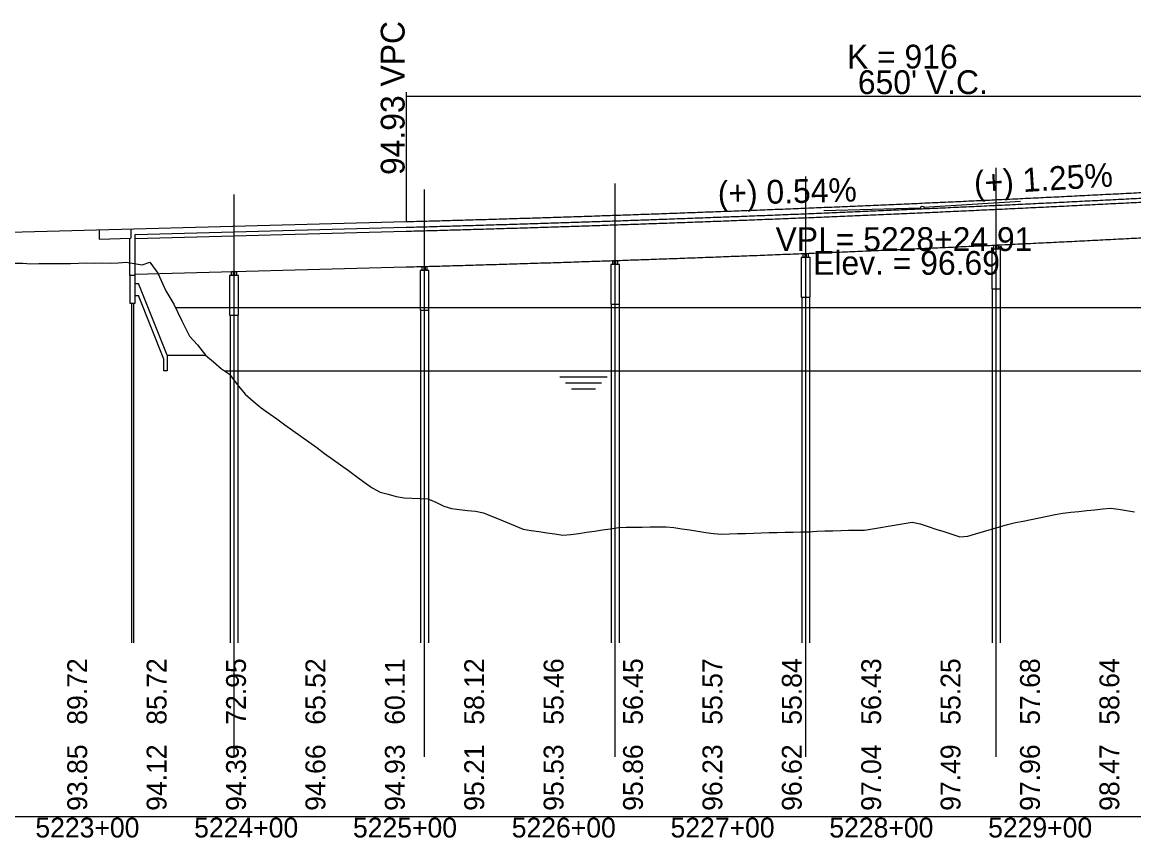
# Model space of a CAD drawing. Extents: x 2121671 to 2169879, y 557274 to 599957.
# Drawn here: x 2151826 to 2152526, y 579173 to 579687 of the extents above; entities that cross this region are included whole.
import ezdxf

# ---------------------------------------------------------------- set-up
doc = ezdxf.new("R2010")
doc.units = 0
for name, color, linetype in [('BR_CENTER LINES', 7, 'Continuous'), ('BR_CONCRETE', 7, 'Continuous'), ('BR_DETAILS', 7, 'Continuous'), ('BR_PRESTRESSED BEAM', 7, 'Continuous'), ('BR_STRUCTURAL STEEL', 7, 'Continuous'), ('RD_DDB_GradeTX', 7, 'Continuous'), ('RD_DDB_Profile_Elev', 7, 'Continuous'), ('RD_DDB_Profile_EX', 7, 'Continuous'), ('RD_DDB_Profile_Lbl', 7, 'Continuous'), ('RD_DDB_Profile_PR', 7, 'Continuous'), ('RD_DDB_StaTX', 7, 'Continuous'), ('RD_DDB_StripGrade', 7, 'Continuous'), ('RD_DDB_VCLbl', 7, 'Continuous'), ('RD_GPK_Profile_Cell', 7, 'Continuous')]:
    doc.layers.add(name, color=color, linetype=linetype)

msp = doc.modelspace()

# ---------------------------------------------------------------- linework, layer by layer
at = {"layer": 'BR_CENTER LINES'}
for p, q in [((2152439.43, 579224.3), (2152439.43, 579595.28)), ((2152319.43, 579224.3), (2152319.43, 579590)), ((2152079.43, 579224.3), (2152079.43, 579581.8)), ((2152199.43, 579224.3), (2152199.43, 579585.51)), ((2151959.43, 579224.3), (2151959.43, 579578.55))]:
    msp.add_line(p, q, dxfattribs=at)
at = {"layer": 'BR_CONCRETE'}
for p, q in [((2151874.43, 579556.26), (2151874.43, 579550.43)), ((2151894.43, 579556.8), (2151894.43, 579550.97)), ((2151897.27, 579553.33), (2152067.84, 579557.94)), ((2151897.27, 579527.54), (2151897.27, 579553.33)), ((2151874.43, 579550.43), (2151894.43, 579550.97)), ((2151893.77, 579527.54), (2151893.77, 579550.95)), ((2152436.93, 579519.17), (2152436.93, 579296.09)), ((2152441.93, 579519.17), (2152441.93, 579296.09)), ((2152196.93, 579509.41), (2152196.93, 579296.09)), ((2152201.93, 579509.41), (2152201.93, 579296.09)), ((2152316.93, 579513.9), (2152316.93, 579296.09)), ((2152321.93, 579513.9), (2152321.93, 579296.09)), ((2151956.93, 579502.47), (2151956.93, 579296.09)), ((2151961.93, 579502.47), (2151961.93, 579296.09)), ((2152076.93, 579505.71), (2152076.93, 579296.09)), ((2152081.93, 579505.71), (2152081.93, 579296.09))]:
    msp.add_line(p, q, dxfattribs=at)
for points in [[(2152436.68, 579519.17), (2152442.18, 579519.17), (2152442.18, 579544.17), (2152436.68, 579544.17)], [(2152316.68, 579513.9), (2152322.18, 579513.9), (2152322.18, 579538.9), (2152316.68, 579538.9)], [(2152076.68, 579505.71), (2152082.18, 579505.71), (2152082.18, 579530.71), (2152076.68, 579530.71)], [(2152196.68, 579509.41), (2152202.18, 579509.41), (2152202.18, 579534.41), (2152196.68, 579534.41)], [(2151893.77, 579510.04), (2151897.27, 579510.04), (2151897.27, 579527.54), (2151893.77, 579527.54)], [(2151956.68, 579502.47), (2151962.18, 579502.47), (2151962.18, 579527.47), (2151956.68, 579527.47)]]:
    msp.add_lwpolyline(points, close=True, dxfattribs=at)
msp.add_spline([(2152067.84, 579557.94), (2152080.84, 579558.29), (2152093.84, 579558.66), (2152106.84, 579559.03), (2152119.84, 579559.42), (2152132.84, 579559.81), (2152145.84, 579560.21), (2152158.84, 579560.62), (2152171.84, 579561.04), (2152184.84, 579561.47), (2152197.84, 579561.91), (2152210.84, 579562.36), (2152223.84, 579562.82), (2152236.84, 579563.28), (2152249.84, 579563.76), (2152262.84, 579564.24), (2152275.84, 579564.74), (2152288.84, 579565.24), (2152301.84, 579565.75), (2152314.84, 579566.27), (2152327.84, 579566.8), (2152340.84, 579567.34), (2152353.84, 579567.89), (2152366.84, 579568.45), (2152379.84, 579569.02), (2152392.84, 579569.6), (2152405.84, 579570.18), (2152418.84, 579570.78), (2152431.84, 579571.38), (2152444.84, 579572), (2152457.84, 579572.62), (2152470.84, 579573.25), (2152483.84, 579573.89), (2152496.84, 579574.55), (2152509.84, 579575.21), (2152522.84, 579575.87), (2152535.84, 579576.55), (2152548.84, 579577.24), (2152561.84, 579577.94), (2152574.84, 579578.64), (2152587.84, 579579.36), (2152600.84, 579580.08), (2152613.84, 579580.82), (2152626.84, 579581.56), (2152639.84, 579582.31), (2152652.84, 579583.08), (2152665.84, 579583.85), (2152678.84, 579584.63), (2152691.84, 579585.42), (2152704.84, 579586.21), (2152717.84, 579587.02)], degree=3, dxfattribs=at)
at = {"layer": 'BR_DETAILS'}
for p, q in [((2151897.27, 579522.54), (2151899.27, 579522.54)), ((2151917.31, 579477.43), (2151899.27, 579522.54)), ((2151897.27, 579515.04), (2151899.27, 579515.04)), ((2151915.31, 579474.93), (2151899.27, 579515.04)), ((2151915.31, 579467.43), (2151915.31, 579474.93)), ((2151917.31, 579477.43), (2151941.42, 579477.43)), ((2151917.31, 579477.43), (2151917.31, 579467.43)), ((2151917.31, 579467.43), (2151915.31, 579467.43))]:
    msp.add_line(p, q, dxfattribs=at)
for points in [[(2152437.93, 579546.67), (2152438.93, 579546.67), (2152438.93, 579544.17), (2152437.93, 579544.17)], [(2152439.93, 579546.67), (2152440.93, 579546.67), (2152440.93, 579544.17), (2152439.93, 579544.17)], [(2152317.93, 579541.4), (2152318.93, 579541.4), (2152318.93, 579538.9), (2152317.93, 579538.9)], [(2152319.93, 579541.4), (2152320.93, 579541.4), (2152320.93, 579538.9), (2152319.93, 579538.9)], [(2152077.93, 579533.21), (2152078.93, 579533.21), (2152078.93, 579530.71), (2152077.93, 579530.71)], [(2152079.93, 579533.21), (2152080.93, 579533.21), (2152080.93, 579530.71), (2152079.93, 579530.71)], [(2152197.93, 579536.91), (2152198.93, 579536.91), (2152198.93, 579534.41), (2152197.93, 579534.41)], [(2152199.93, 579536.91), (2152200.93, 579536.91), (2152200.93, 579534.41), (2152199.93, 579534.41)], [(2151957.93, 579529.97), (2151958.93, 579529.97), (2151958.93, 579527.47), (2151957.93, 579527.47)], [(2151959.93, 579529.97), (2151960.93, 579529.97), (2151960.93, 579527.47), (2151959.93, 579527.47)]]:
    msp.add_lwpolyline(points, close=True, dxfattribs=at)
at = {"layer": 'BR_PRESTRESSED BEAM'}
for p, q in [((2151897.27, 579550.83), (2152067.84, 579555.44)), ((2151897.27, 579528.33), (2152067.84, 579532.94))]:
    msp.add_line(p, q, dxfattribs=at)
for points in [[(2152067.84, 579555.44), (2152080.84, 579555.79), (2152093.84, 579556.16), (2152106.84, 579556.53), (2152119.84, 579556.92), (2152132.84, 579557.31), (2152145.84, 579557.71), (2152158.84, 579558.12), (2152171.84, 579558.54), (2152184.84, 579558.97), (2152197.84, 579559.41), (2152210.84, 579559.86), (2152223.84, 579560.32), (2152236.84, 579560.78), (2152249.84, 579561.26), (2152262.84, 579561.74), (2152275.84, 579562.24), (2152288.84, 579562.74), (2152301.84, 579563.25), (2152314.84, 579563.77), (2152327.84, 579564.3), (2152340.84, 579564.84), (2152353.84, 579565.39), (2152366.84, 579565.95), (2152379.84, 579566.52), (2152392.84, 579567.1), (2152405.84, 579567.68), (2152418.84, 579568.28), (2152431.84, 579568.88), (2152444.84, 579569.5), (2152457.84, 579570.12), (2152470.84, 579570.75), (2152483.84, 579571.39), (2152496.84, 579572.05), (2152509.84, 579572.71), (2152522.84, 579573.37), (2152535.84, 579574.05), (2152548.84, 579574.74), (2152561.84, 579575.44), (2152574.84, 579576.14), (2152587.84, 579576.86), (2152600.84, 579577.58), (2152613.84, 579578.32), (2152626.84, 579579.06), (2152639.84, 579579.81), (2152652.84, 579580.58), (2152665.84, 579581.35), (2152678.84, 579582.13), (2152691.84, 579582.92), (2152704.84, 579583.71), (2152717.84, 579584.52)], [(2152067.84, 579532.94), (2152080.84, 579533.29), (2152093.84, 579533.66), (2152106.84, 579534.03), (2152119.84, 579534.42), (2152132.84, 579534.81), (2152145.84, 579535.21), (2152158.84, 579535.62), (2152171.84, 579536.04), (2152184.84, 579536.47), (2152197.84, 579536.91), (2152210.84, 579537.36), (2152223.84, 579537.82), (2152236.84, 579538.28), (2152249.84, 579538.76), (2152262.84, 579539.24), (2152275.84, 579539.74), (2152288.84, 579540.24), (2152301.84, 579540.75), (2152314.84, 579541.27), (2152327.84, 579541.8), (2152340.84, 579542.34), (2152353.84, 579542.89), (2152366.84, 579543.45), (2152379.84, 579544.02), (2152392.84, 579544.6), (2152405.84, 579545.18), (2152418.84, 579545.78), (2152431.84, 579546.38), (2152444.84, 579547), (2152457.84, 579547.62), (2152470.84, 579548.25), (2152483.84, 579548.89), (2152496.84, 579549.55), (2152509.84, 579550.21), (2152522.84, 579550.87), (2152535.84, 579551.55), (2152548.84, 579552.24), (2152561.84, 579552.94), (2152574.84, 579553.64), (2152587.84, 579554.36), (2152600.84, 579555.08), (2152613.84, 579555.82), (2152626.84, 579556.56), (2152639.84, 579557.31), (2152652.84, 579558.08), (2152665.84, 579558.85), (2152678.84, 579559.63), (2152691.84, 579560.42), (2152704.84, 579561.21), (2152717.84, 579562.02)]]:
    msp.add_spline(points, degree=3, dxfattribs=at)
at = {"layer": 'BR_STRUCTURAL STEEL'}
for p, q in [((2151894.93, 579510.04), (2151894.93, 579296.09)), ((2151896.1, 579510.04), (2151896.1, 579296.09))]:
    msp.add_line(p, q, dxfattribs=at)
at = {"layer": 'RD_DDB_GradeTX'}
for p, q in [((2152454.72, 579574.12), (2152393.84, 579570.32)), ((2152330.87, 579568.58), (2152391.84, 579570.23))]:
    msp.add_line(p, q, dxfattribs=at)
msp.add_circle((2152392.84, 579570.26), 1, dxfattribs=at)
at = {"layer": 'RD_DDB_Profile_Elev'}
for p, q in [((2151922.43, 579507.43), (2155499.43, 579507.43)), ((2151953.51, 579467.43), (2156316.65, 579467.43)), ((2152164.52, 579463.68), (2152194.52, 579463.68)), ((2152168.27, 579459.93), (2152190.77, 579459.93)), ((2152172.02, 579456.18), (2152187.02, 579456.18))]:
    msp.add_line(p, q, dxfattribs=at)
at = {"layer": 'RD_DDB_Profile_EX'}
for points in [[(2151821.48, 579535.34), (2151826.48, 579535.31), (2151831.48, 579534.89), (2151836.48, 579535.06), (2151841.48, 579535.2), (2151846.48, 579535.14), (2151851.48, 579535.04), (2151856.48, 579535.15), (2151861.48, 579535.34), (2151866.48, 579535.5), (2151871.48, 579535.33), (2151876.48, 579535.43), (2151881.48, 579535.37), (2151886.48, 579535.61), (2151891.48, 579535.87), (2151896.48, 579535.04), (2151901.48, 579534.3), (2151906.48, 579535.89), (2151911.48, 579528.98), (2151916.48, 579517.87), (2151921.48, 579509.4), (2151926.48, 579499.02), (2151931.48, 579489.36), (2151936.48, 579483.82), (2151941.48, 579477.34), (2151946.48, 579473.09), (2151951.48, 579468.83), (2151956.48, 579465.38), (2151961.48, 579458.79), (2151966.48, 579452.85), (2151971.48, 579448.44), (2151976.48, 579444.15), (2151981.48, 579440.71), (2151986.48, 579437.18), (2151991.48, 579433.56), (2151996.48, 579429.95), (2152001.48, 579426.33), (2152006.48, 579422.71), (2152011.48, 579419.1), (2152016.48, 579415.48), (2152021.48, 579411.86), (2152026.48, 579408.25), (2152031.48, 579404.63), (2152036.48, 579401.01), (2152041.48, 579397.4), (2152046.48, 579393.78), (2152051.48, 579391.16), (2152056.48, 579389.75), (2152061.48, 579388.33), (2152066.48, 579387.46), (2152071.48, 579387.24), (2152076.48, 579387.01), (2152081.48, 579386.79), (2152086.48, 579384.74), (2152091.48, 579382.28), (2152096.48, 579380.78), (2152101.48, 579380.19), (2152106.48, 579379.61), (2152111.48, 579379.02), (2152116.48, 579377.99), (2152121.48, 579375.97), (2152126.48, 579373.96), (2152131.48, 579371.94), (2152136.48, 579369.92), (2152141.48, 579367.66), (2152146.48, 579366.93), (2152151.48, 579366.2), (2152156.48, 579365.47), (2152161.48, 579364.75), (2152166.48, 579364.02), (2152171.48, 579364.36), (2152176.48, 579365.12), (2152181.48, 579365.85), (2152186.48, 579366.58), (2152191.48, 579367.31), (2152196.48, 579368.03), (2152201.48, 579368.74), (2152206.48, 579368.91), (2152211.48, 579368.98), (2152216.48, 579369.05), (2152221.48, 579369.13)], [(2152221.48, 579369.13), (2152226.48, 579369.2), (2152231.48, 579369.17), (2152236.48, 579368.84), (2152241.48, 579368.06), (2152246.48, 579367.27), (2152251.48, 579366.49), (2152256.48, 579365.71), (2152261.48, 579364.92), (2152266.48, 579364.62), (2152271.48, 579364.77), (2152276.48, 579364.93), (2152281.48, 579365.08), (2152286.48, 579365.23), (2152291.48, 579365.38), (2152296.48, 579365.61), (2152301.48, 579365.71), (2152306.48, 579365.81), (2152311.48, 579365.91), (2152316.48, 579366.02), (2152321.48, 579366.12), (2152326.48, 579366.49), (2152331.48, 579366.63), (2152336.48, 579366.77), (2152341.48, 579366.9), (2152346.48, 579367.04), (2152351.48, 579367.18), (2152356.48, 579367.19), (2152361.48, 579367.91), (2152366.48, 579368.74), (2152371.48, 579369.57), (2152376.48, 579370.4), (2152381.48, 579371.23), (2152386.48, 579372.06), (2152391.48, 579371.02), (2152396.48, 579369.41), (2152401.48, 579367.79), (2152406.48, 579366.18), (2152411.48, 579364.56), (2152416.48, 579362.95), (2152421.48, 579363.4), (2152426.48, 579364.86), (2152431.48, 579366.33), (2152436.48, 579367.79), (2152441.48, 579369.26), (2152446.48, 579370.72), (2152451.48, 579371.86), (2152456.48, 579372.89), (2152461.48, 579373.92), (2152466.48, 579374.95), (2152471.48, 579375.97), (2152476.48, 579377), (2152481.48, 579377.88), (2152486.48, 579378.4), (2152491.48, 579378.93), (2152496.48, 579379.45), (2152501.48, 579379.97), (2152506.48, 579380.49), (2152511.48, 579381.02), (2152516.48, 579380.26), (2152521.48, 579379.48), (2152526.48, 579378.7)]]:
    msp.add_lwpolyline(points, dxfattribs=at)
at = {"layer": 'RD_DDB_Profile_PR'}
msp.add_line((2151221.48, 579538.63), (2152067.84, 579561.48), dxfattribs=at)
msp.add_spline([(2152067.84, 579561.48), (2152080.84, 579561.84), (2152093.84, 579562.2), (2152106.84, 579562.57), (2152119.84, 579562.96), (2152132.84, 579563.35), (2152145.84, 579563.75), (2152158.84, 579564.16), (2152171.84, 579564.58), (2152184.84, 579565.01), (2152197.84, 579565.45), (2152210.84, 579565.9), (2152223.84, 579566.36), (2152236.84, 579566.82), (2152249.84, 579567.3), (2152262.84, 579567.78), (2152275.84, 579568.28), (2152288.84, 579568.78), (2152301.84, 579569.29), (2152314.84, 579569.81), (2152327.84, 579570.35), (2152340.84, 579570.89), (2152353.84, 579571.44), (2152366.84, 579571.99), (2152379.84, 579572.56), (2152392.84, 579573.14), (2152405.84, 579573.72), (2152418.84, 579574.32), (2152431.84, 579574.93), (2152444.84, 579575.54), (2152457.84, 579576.16), (2152470.84, 579576.79), (2152483.84, 579577.44), (2152496.84, 579578.09), (2152509.84, 579578.75), (2152522.84, 579579.42), (2152535.84, 579580.1), (2152548.84, 579580.78), (2152561.84, 579581.48), (2152574.84, 579582.19), (2152587.84, 579582.9), (2152600.84, 579583.63), (2152613.84, 579584.36), (2152626.84, 579585.1), (2152639.84, 579585.86), (2152652.84, 579586.62), (2152665.84, 579587.39), (2152678.84, 579588.17), (2152691.84, 579588.96), (2152704.84, 579589.76), (2152717.84, 579590.56)], degree=3, dxfattribs=at)
at = {"layer": 'RD_DDB_VCLbl'}
for p, q in [((2152067.84, 579643.06), (2152067.84, 579561.48)), ((2152067.84, 579640.56), (2152717.84, 579640.56))]:
    msp.add_line(p, q, dxfattribs=at)
at = {"layer": 'RD_GPK_Profile_Cell'}
msp.add_line((2151067.93, 579186.83), (2157367.93, 579186.83), dxfattribs=at)

# ---------------------------------------------------------------- texts
at = {"layer": 'RD_DDB_GradeTX'}
for s, rotation, p in [('(+) 1.25%', 3.57557, (2152425.87, 579578.16)), ('(+) 0.54%', 1.54661, (2152264.27, 579571.83))]:
    msp.add_text(s, height=15, rotation=rotation, dxfattribs=at).set_placement(p)
at = {"layer": 'RD_DDB_Profile_Lbl'}
for s, p in [('VPI = 5228+24.91', (2152300.48, 579542.97)), ('Elev. = 96.69', (2152324.12, 579527.97))]:
    msp.add_text(s, height=15, dxfattribs=at).set_placement(p)
at = {"layer": 'RD_DDB_StaTX'}
for s, p in [('5223+00', (2151834.32, 579173.53)), ('5224+00', (2151934.32, 579173.53)), ('5225+00', (2152034.32, 579173.53)), ('5226+00', (2152134.32, 579173.53)), ('5227+00', (2152234.32, 579173.53)), ('5228+00', (2152334.32, 579173.53)), ('5229+00', (2152434.32, 579173.53))]:
    msp.add_text(s, height=12.5, dxfattribs=at).set_placement(p)
at = {"layer": 'RD_DDB_StripGrade'}
for s, height, p in [('94.93 VPC', 15, (2152066.84, 579590.83)), ('89.72', 12.5, (2151866.93, 579244.56)), ('85.72', 12.5, (2151916.93, 579244.56)), ('72.95', 12.5, (2151966.93, 579244.56)), ('65.52', 12.5, (2152016.93, 579244.56)), ('60.11', 12.5, (2152066.93, 579244.56)), ('58.12', 12.5, (2152116.93, 579244.56)), ('55.46', 12.5, (2152166.93, 579244.56)), ('56.45', 12.5, (2152216.93, 579244.56)), ('55.57', 12.5, (2152266.93, 579244.56)), ('55.84', 12.5, (2152316.93, 579244.56)), ('56.43', 12.5, (2152366.93, 579244.56)), ('55.25', 12.5, (2152416.93, 579244.56)), ('57.68', 12.5, (2152466.93, 579244.56)), ('58.64', 12.5, (2152516.93, 579244.56)), ('93.85', 12.5, (2151866.93, 579190.33)), ('94.12', 12.5, (2151916.93, 579190.33)), ('94.39', 12.5, (2151966.93, 579190.33)), ('94.66', 12.5, (2152016.93, 579190.33)), ('94.93', 12.5, (2152066.93, 579190.33)), ('95.21', 12.5, (2152116.93, 579190.33)), ('95.53', 12.5, (2152166.93, 579190.33)), ('95.86', 12.5, (2152216.93, 579190.33)), ('96.23', 12.5, (2152266.93, 579190.33)), ('96.62', 12.5, (2152316.93, 579190.33)), ('97.04', 12.5, (2152366.93, 579190.33)), ('97.49', 12.5, (2152416.93, 579190.33)), ('97.96', 12.5, (2152466.93, 579190.33)), ('98.47', 12.5, (2152516.93, 579190.33))]:
    msp.add_text(s, height=height, rotation=90, dxfattribs=at).set_placement(p)
at = {"layer": 'RD_DDB_VCLbl'}
for s, p in [('K = 916', (2152345.43, 579657.92)), ("650' V.C.", (2152352.29, 579641.81))]:
    msp.add_text(s, height=15, dxfattribs=at).set_placement(p)

doc.saveas('drawing.dxf')
